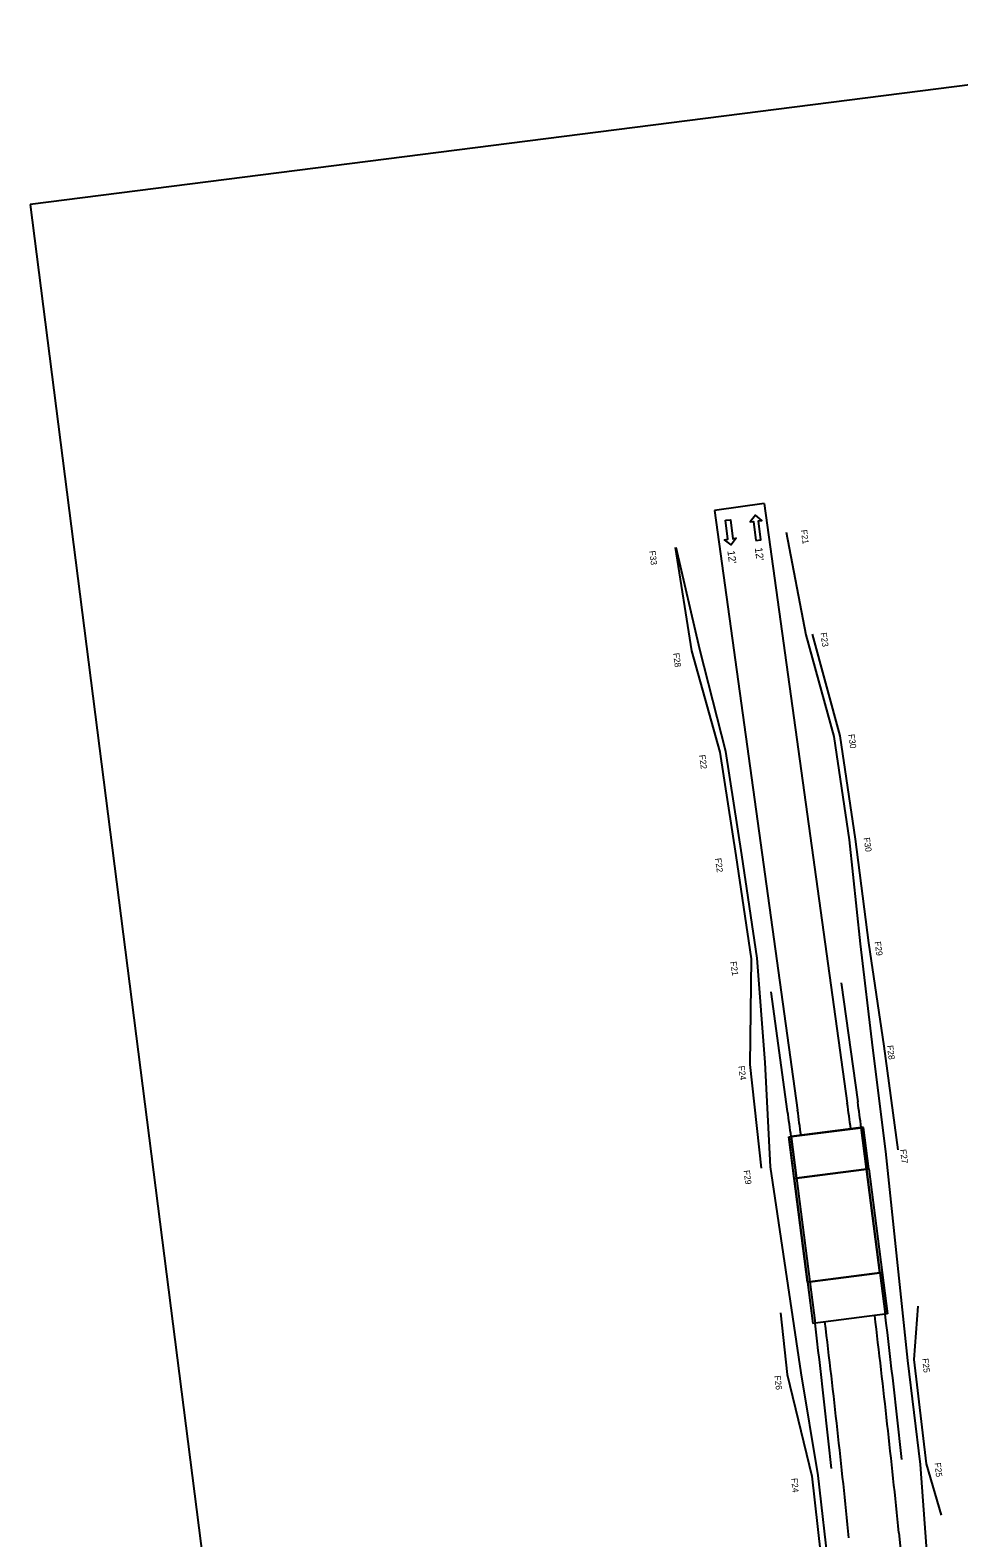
# Model space of a CAD drawing. Extents: x 1740945 to 1741736, y 1214636 to 1217912.
# Drawn here: x 1740945 to 1741389, y 1217191 to 1217912 of the extents above; entities that cross this region are included whole.
import ezdxf

# ---------------------------------------------------------------- set-up
doc = ezdxf.new("R2010")
doc.units = 0
for name, color, linetype in [('Default', 7, 'Continuous'), ('RD_PD_Bridge', 7, 'Continuous'), ('RD_PD_CstnLmt', 7, 'Continuous'), ('RD_PD_CstnLmt_TX', 7, 'Continuous'), ('RD_PD_DR_ErosCtrl', 7, 'Continuous'), ('RD_PD_Final_TrvlWay', 7, 'Continuous'), ('RD_PD_Final_TX', 7, 'Continuous'), ('RD_PD_GR', 7, 'Continuous'), ('RD_SHT_TX', 7, 'Continuous'), ('RD_Sketch2', 7, 'Continuous')]:
    doc.layers.add(name, color=color, linetype=linetype)

msp = doc.modelspace()

# ---------------------------------------------------------------- linework, layer by layer
at = {"layer": 'Default'}
for p, q in [((1741310.67, 1217362.83), (1741308.13, 1217382.66)), ((1741346.29, 1217367.4), (1741343.75, 1217387.23)), ((1741310.75, 1217362.84), (1741317.11, 1217313.24)), ((1741352.74, 1217317.81), (1741355.28, 1217297.98)), ((1741317.03, 1217313.23), (1741319.57, 1217293.4))]:
    msp.add_line(p, q, dxfattribs=at)
at = {"layer": 'RD_PD_Bridge'}
for p, q in [((1741308.13, 1217382.66), (1741343.83, 1217387.24)), ((1741310.75, 1217362.84), (1741308.21, 1217382.68)), ((1741342.76, 1217387.11), (1741309.2, 1217382.8)), ((1741311.74, 1217362.97), (1741309.2, 1217382.8)), ((1741309.2, 1217382.8), (1741311.74, 1217362.97)), ((1741343.83, 1217387.24), (1741342.76, 1217387.11)), ((1741345.3, 1217367.27), (1741342.76, 1217387.11)), ((1741345.3, 1217367.27), (1741342.76, 1217387.11)), ((1741342.76, 1217387.11), (1741345.3, 1217367.27)), ((1741346.38, 1217367.41), (1741343.83, 1217387.24)), ((1741346.38, 1217367.41), (1741343.83, 1217387.24)), ((1741345.3, 1217367.27), (1741311.74, 1217362.97)), ((1741311.74, 1217362.97), (1741345.3, 1217367.27)), ((1741345.3, 1217367.27), (1741311.74, 1217362.97)), ((1741345.3, 1217367.27), (1741311.74, 1217362.97)), ((1741345.3, 1217367.27), (1741346.38, 1217367.41)), ((1741345.3, 1217367.27), (1741351.66, 1217317.68)), ((1741351.66, 1217317.68), (1741345.3, 1217367.27)), ((1741351.66, 1217317.68), (1741345.3, 1217367.27)), ((1741351.66, 1217317.68), (1741345.3, 1217367.27)), ((1741311.74, 1217362.97), (1741318.1, 1217313.37)), ((1741311.74, 1217362.97), (1741318.1, 1217313.37)), ((1741311.74, 1217362.97), (1741318.1, 1217313.37)), ((1741311.74, 1217362.97), (1741318.1, 1217313.37)), ((1741318.1, 1217313.37), (1741351.66, 1217317.68)), ((1741318.1, 1217313.37), (1741351.66, 1217317.68)), ((1741318.1, 1217313.37), (1741351.66, 1217317.68)), ((1741351.66, 1217317.68), (1741354.21, 1217297.84)), ((1741352.65, 1217317.8), (1741355.2, 1217297.97)), ((1741317.11, 1217313.24), (1741319.66, 1217293.41)), ((1741318.1, 1217313.37), (1741320.65, 1217293.53)), ((1741355.28, 1217297.98), (1741319.57, 1217293.4))]:
    msp.add_line(p, q, dxfattribs=at)
msp.add_lwpolyline([(1741346.38, 1217367.41), (1741352.74, 1217317.81), (1741317.03, 1217313.23), (1741310.67, 1217362.83)], close=True, dxfattribs=at)
at = {"layer": 'RD_PD_CstnLmt'}
for p, q in [((1741306.9, 1217672.05), (1741316.28, 1217622.87)), ((1741265.6, 1217615.86), (1741254.18, 1217664.75)), ((1741316.28, 1217622.87), (1741329.6, 1217574.24)), ((1741278.05, 1217567.1), (1741265.6, 1217615.86)), ((1741329.6, 1217574.24), (1741336.94, 1217524.78)), ((1741285.69, 1217517.68), (1741278.05, 1217567.1)), ((1741336.94, 1217524.78), (1741342.19, 1217475.03)), ((1741293.01, 1217468.22), (1741285.69, 1217517.68)), ((1741342.19, 1217475.03), (1741348.06, 1217425.36)), ((1741296.77, 1217418.27), (1741293.01, 1217468.22)), ((1741348.06, 1217425.36), (1741354.34, 1217375.64)), ((1741299.34, 1217368.27), (1741296.77, 1217418.27)), ((1741354.34, 1217375.64), (1741364.91, 1217275.72)), ((1741314.08, 1217269.82), (1741299.34, 1217368.27)), ((1741364.91, 1217275.72), (1741370.86, 1217225.86)), ((1741322.14, 1217220.63), (1741314.08, 1217269.82)), ((1741370.86, 1217225.86), (1741374.62, 1217175.91)), ((1741327.72, 1217171.06), (1741322.14, 1217220.63))]:
    msp.add_line(p, q, dxfattribs=at)
at = {"layer": 'RD_PD_DR_ErosCtrl'}
for points in [[(1741253.83, 1217664.7), (1741261.63, 1217615.31), (1741275.08, 1217566.69), (1741282.72, 1217517.27), (1741290.04, 1217467.81), (1741289.55, 1217417.27), (1741294.89, 1217367.68)], [(1741319.26, 1217623.28), (1741332.58, 1217574.65), (1741339.77, 1217525.17), (1741346.16, 1217475.58), (1741353.49, 1217426.12), (1741360.31, 1217376.44)], [(1741304.12, 1217298.5), (1741307.36, 1217269.04), (1741319.16, 1217220.3), (1741324.73, 1217170.76), (1741325.8, 1217120.61), (1741328.02, 1217070.58), (1741341.76, 1217021.72)], [(1741369.83, 1217301.61), (1741367.89, 1217276.07), (1741373.84, 1217226.18), (1741381, 1217201.66)]]:
    msp.add_lwpolyline(points, dxfattribs=at)
at = {"layer": 'RD_PD_Final_TrvlWay'}
for p, q in [((1741296.35, 1217685.73), (1741272.57, 1217682.44)), ((1741296.35, 1217685.73), (1741336.07, 1217398.75)), ((1741272.57, 1217682.44), (1741312.3, 1217395.46)), ((1741360.76, 1217193.24), (1741377.85, 1217025.39))]:
    msp.add_line(p, q, dxfattribs=at)
for radius, start, end in [(5741.64, 7.757463, 7.881242), (5717.64, 7.75935, 7.88124), (5741.64, 5.815562, 6.859345), (5717.64, 5.81556, 6.85746)]:
    msp.add_arc((1735648.67, 1216611.46), radius, start, end, dxfattribs=at)
at = {"layer": 'RD_PD_Final_TX'}
for points in [[(1741277.91, 1217677.73), (1741280.29, 1217678.01), (1741281.37, 1217668.9), (1741282.98, 1217669.09), (1741280.5, 1217665.95), (1741277.37, 1217668.43), (1741278.98, 1217668.62)], [(1741292.34, 1217668.1), (1741294.72, 1217668.38), (1741293.65, 1217677.49), (1741295.27, 1217677.68), (1741292.13, 1217680.16), (1741289.65, 1217677.02), (1741291.27, 1217677.21)]]:
    msp.add_lwpolyline(points, close=True, dxfattribs=at)
at = {"layer": 'RD_PD_GR'}
for p, q in [((1741333.17, 1217456.46), (1741341.06, 1217399.45)), ((1741307.55, 1217394.81), (1741299.61, 1217452.14))]:
    msp.add_line(p, q, dxfattribs=at)
for radius, start, end in [(5746.68, 7.757151, 7.881242), (5712.85, 7.75966, 7.88124), (5746.68, 6.161542, 6.859657), (5712.85, 6.15512, 6.85714)]:
    msp.add_arc((1735648.67, 1216611.46), radius, start, end, dxfattribs=at)
at = {"layer": 'RD_Sketch2'}
msp.add_lwpolyline([(1740945.32, 1217828.9), (1741081.72, 1216757.55), (1741736.44, 1216840.9), (1741600.04, 1217912.26)], close=True, dxfattribs=at)

# ---------------------------------------------------------------- texts
at = {"layer": 'RD_PD_CstnLmt_TX'}
for s, rotation, p in [('F21', 277.88124, (1741313.84, 1217673.01)), ('F33', 277.88124, (1741241.3, 1217662.97)), ('F23', 277.88124, (1741323.22, 1217623.83)), ('F28', 277.88124, (1741252.72, 1217614.07)), ('F30', 277.88124, (1741336.54, 1217575.2)), ('F22', 277.88124, (1741265.17, 1217565.32)), ('F30', 277.88124, (1741343.88, 1217525.74)), ('F22', 277.88124, (1741272.81, 1217515.9)), ('F29', 277.88124, (1741349.13, 1217475.99)), ('F21', 277.88124, (1741280.13, 1217466.44)), ('F28', 277.88124, (1741354.99, 1217426.32)), ('F24', 277.88124, (1741283.9, 1217416.48)), ('F27', 277.6284, (1741361.28, 1217376.57)), ('F29', 277.6284, (1741286.46, 1217366.55)), ('F25', 276.62841, (1741371.86, 1217276.53)), ('F26', 276.62841, (1741301.17, 1217268.32)), ('F25', 276.12842, (1741377.82, 1217226.6)), ('F24', 276.12842, (1741309.22, 1217219.24))]:
    msp.add_text(s, height=3, rotation=rotation, dxfattribs=at).set_placement(p)
at = {"layer": 'RD_SHT_TX'}
for p in [(1741278.71, 1217663.03), (1741291.84, 1217664.47)]:
    msp.add_text("12'", height=3.6, rotation=277.58057, dxfattribs=at).set_placement(p)

doc.saveas('drawing.dxf')
